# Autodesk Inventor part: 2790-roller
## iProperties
Author: Administrator
Shininess: 64.0
Angle Display Precision: 2
Document Length Units: 11272
Document Angle Units: 11286
Document Time Units: 11279
Document Mass Units: 11290
Document Length Units Precision: 3
Document Angle Units Precision: 2
Compacted: True
PropertySet Name: _Private Model Information
Created: 2002-03
Part Number: 2790-roller
Material: Stainless Steel, 440C
Document SubType Name: Modeling
Designer: Administrator
Control State: 0
Master: False
Checked Out: False
PropertySet Name: Design Tracking Control
Density: 0.0
Volumn: 0.0
Area: 0.0
PropertySet Name: Model Information
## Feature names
1. Revolution1
